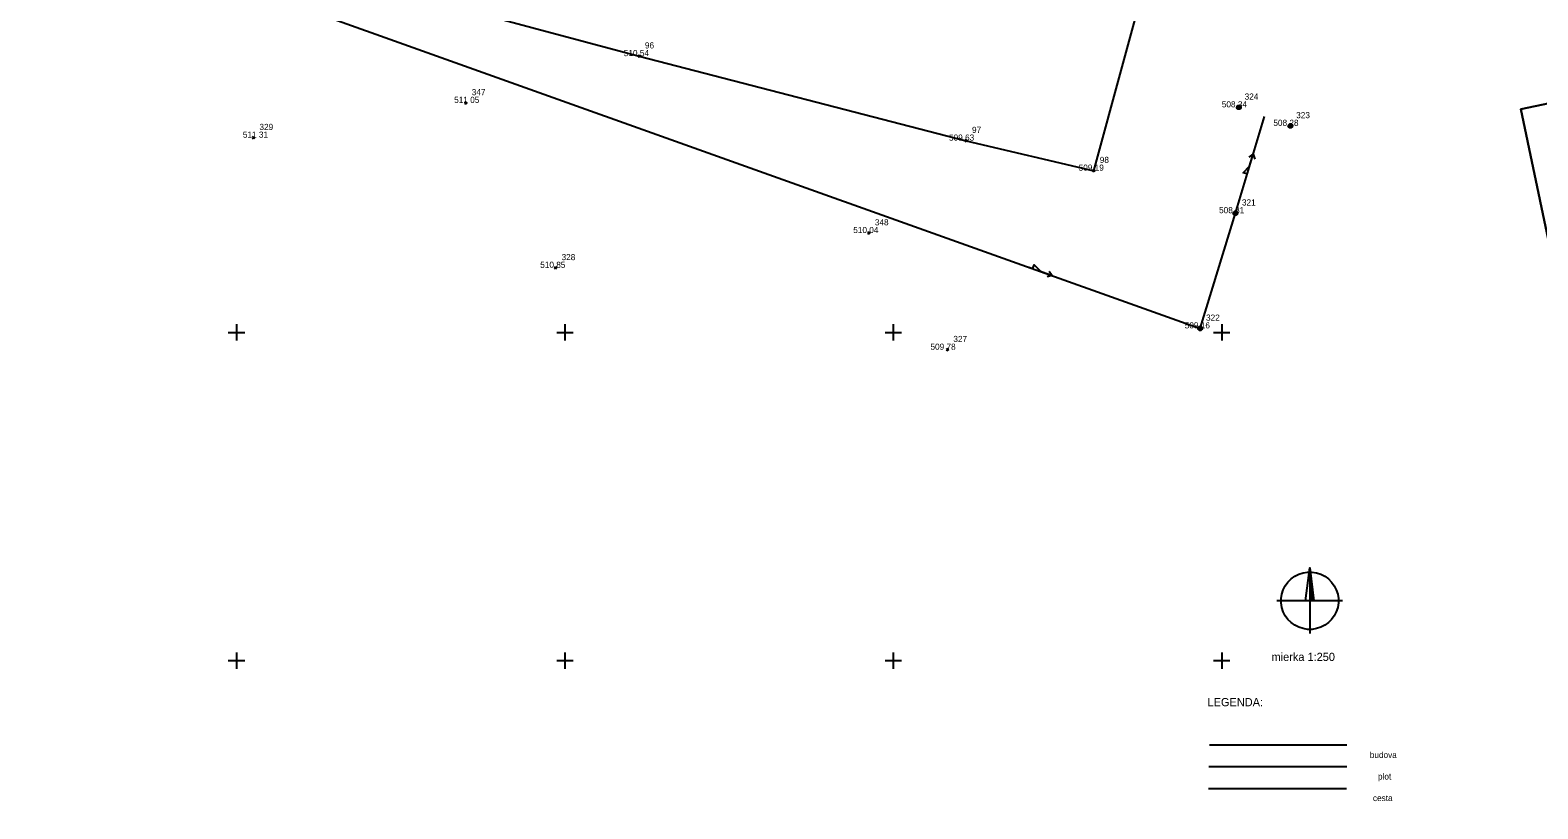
# Model space of a CAD drawing. Extents: x -408550 to -407654, y -1233019 to -1231230.
# Drawn here: x -407992.6 to -407900.7, y -1232149 to -1232101.6 of the extents above; entities that cross this region are included whole.
import ezdxf

# ---------------------------------------------------------------- set-up
doc = ezdxf.new("R2010")
doc.units = 0
for name, color, linetype in [('Level 1', 7, 'Continuous'), ('Level 11', 7, 'Continuous'), ('Level 12', 7, 'Continuous'), ('Level 14', 7, 'Continuous'), ('Level 22', 7, 'Continuous'), ('Level 23', 7, 'Continuous'), ('Level 25', 7, 'Continuous'), ('Level 26', 7, 'Continuous'), ('Level 40', 7, 'Continuous'), ('Level 45', 7, 'Continuous')]:
    doc.layers.add(name, color=color, linetype=linetype)

msp = doc.modelspace()

# ---------------------------------------------------------------- linework, layer by layer
at = {"layer": 'Level 1'}
for p, q in [((-407980.5, -1232120), (-407979.5, -1232120)), ((-407980, -1232119.5), (-407980, -1232120.5)), ((-407960.5, -1232120), (-407959.5, -1232120)), ((-407960, -1232119.5), (-407960, -1232120.5)), ((-407940.5, -1232120), (-407939.5, -1232120)), ((-407940, -1232119.5), (-407940, -1232120.5)), ((-407920.5, -1232120), (-407919.5, -1232120)), ((-407920, -1232119.5), (-407920, -1232120.5)), ((-407980, -1232139.5), (-407980, -1232140.5)), ((-407960, -1232139.5), (-407960, -1232140.5)), ((-407940, -1232139.5), (-407940, -1232140.5)), ((-407920, -1232139.5), (-407920, -1232140.5)), ((-407980.5, -1232140), (-407979.5, -1232140)), ((-407960.5, -1232140), (-407959.5, -1232140)), ((-407940.5, -1232140), (-407939.5, -1232140)), ((-407920.5, -1232140), (-407919.5, -1232140))]:
    msp.add_line(p, q, dxfattribs=at)
for points in [[(-408044.77, -1232071.09), (-408035.27, -1232074.4), (-408023.96, -1232078.34), (-408004.8, -1232085.03), (-407985.8, -1232091.65), (-407974.67, -1232095.53), (-407964.75, -1232098.99), (-407959.41, -1232100.85), (-407865.11, -1232098.76), (-407866.39, -1232098.97), (-407901.79, -1232106.39), (-407899.44, -1232117.51), (-407894.61, -1232140.35), (-407874.15, -1232135.48), (-407862.74, -1232131.55), (-407855.39, -1232125.61), (-407852.28, -1232122.69), (-407848.72, -1232121.07), (-407838.47, -1232120.5), (-407847.32, -1232123.67), (-407848.36, -1232134.5), (-407841.61, -1232145.17), (-407846.34, -1232175.35)], [(-407899.44, -1232117.51), (-407901.79, -1232106.39), (-407866.39, -1232098.97)], [(-407914.889, -1232136.352), (-407914.639, -1232134.352), (-407914.389, -1232136.352), (-407914.409, -1232136.332), (-407914.409, -1232136.212), (-407914.429, -1232136.052), (-407914.429, -1232136.332), (-407914.449, -1232136.332), (-407914.449, -1232135.892), (-407914.469, -1232135.732), (-407914.469, -1232136.332), (-407914.489, -1232136.332), (-407914.489, -1232135.572), (-407914.509, -1232135.432), (-407914.509, -1232136.332), (-407914.529, -1232136.332), (-407914.529, -1232135.272), (-407914.549, -1232135.092), (-407914.549, -1232136.332), (-407914.569, -1232136.332), (-407914.569, -1232134.952), (-407914.589, -1232134.772), (-407914.589, -1232136.332), (-407914.609, -1232136.332), (-407914.609, -1232134.612), (-407914.629, -1232134.452), (-407914.629, -1232136.332)], [(-407914.639, -1232134.352), (-407914.639, -1232138.352)], [(-407912.639, -1232136.352), (-407916.639, -1232136.352)]]:
    msp.add_lwpolyline(points, dxfattribs=at)
msp.add_lwpolyline([(-407914.501, -1232134.607), (-407914.231, -1232134.649), (-407913.971, -1232134.734), (-407913.726, -1232134.859), (-407913.504, -1232135.022), (-407913.309, -1232135.217), (-407913.146, -1232135.439), (-407913.021, -1232135.684), (-407912.936, -1232135.944), (-407912.894, -1232136.214), (-407912.894, -1232136.489), (-407912.936, -1232136.759), (-407913.021, -1232137.019), (-407913.146, -1232137.264), (-407913.309, -1232137.487), (-407913.504, -1232137.682), (-407913.726, -1232137.844), (-407913.971, -1232137.969), (-407914.231, -1232138.054), (-407914.501, -1232138.097), (-407914.776, -1232138.097), (-407915.046, -1232138.054), (-407915.306, -1232137.969), (-407915.551, -1232137.844), (-407915.774, -1232137.682), (-407915.969, -1232137.487), (-407916.131, -1232137.264), (-407916.256, -1232137.019), (-407916.341, -1232136.759), (-407916.384, -1232136.489), (-407916.384, -1232136.214), (-407916.341, -1232135.944), (-407916.256, -1232135.684), (-407916.131, -1232135.439), (-407915.969, -1232135.217), (-407915.774, -1232135.022), (-407915.551, -1232134.859), (-407915.306, -1232134.734), (-407915.046, -1232134.649), (-407914.776, -1232134.607)], close=True, dxfattribs=at)
at = {"layer": 'Level 11'}
msp.add_line((-407912.383, -1232145.158), (-407920.742, -1232145.158), dxfattribs=at)
at = {"layer": 'Level 12'}
msp.add_line((-407912.383, -1232146.474), (-407920.787, -1232146.474), dxfattribs=at)
msp.add_lwpolyline([(-408056.73, -1232038.31), (-408035.18, -1232049.43), (-408016.67, -1232058.98), (-407995.64, -1232070.23), (-407983.94, -1232082.87), (-407968.55, -1232099.65), (-407955.47, -1232103.17), (-407935.56, -1232108.32), (-407927.78, -1232110.15), (-407922.43, -1232090.45), (-407918.07, -1232073.76), (-407912.71, -1232053.79), (-407910.82, -1232047.19), (-407908.67, -1232042.13), (-407906.88, -1232038.31), (-407908.34, -1232037.12), (-407921.23, -1232026.55), (-407939.09, -1232011.64)], dxfattribs=at)
at = {"layer": 'Level 14'}
msp.add_line((-407912.406, -1232147.808), (-407920.806, -1232147.808), dxfattribs=at)
at = {"layer": 'Level 22'}
msp.add_line((-407927.78, -1232110.15), (-407927.78, -1232110.15), dxfattribs=at)
msp.add_lwpolyline([(-408151.19, -1232037.68), (-408071.39, -1232066.44), (-407993.81, -1232093.84), (-407921.31, -1232119.76), (-407919.17, -1232112.74), (-407917.389, -1232106.855)], dxfattribs=at)
at = {"layer": 'Level 23'}
for points in [[(-407955.401, -1232103.239), (-407955.539, -1232103.101)], [(-407955.539, -1232103.239), (-407955.401, -1232103.101)], [(-407965.961, -1232106.089), (-407966.099, -1232105.951)], [(-407966.099, -1232106.089), (-407965.961, -1232105.951)], [(-407918.891, -1232106.359), (-407919.029, -1232106.221)], [(-407919.029, -1232106.359), (-407918.891, -1232106.221)], [(-407915.751, -1232107.489), (-407915.889, -1232107.351)], [(-407915.889, -1232107.489), (-407915.751, -1232107.351)], [(-407978.891, -1232108.209), (-407979.029, -1232108.071)], [(-407979.029, -1232108.209), (-407978.891, -1232108.071)], [(-407935.491, -1232108.389), (-407935.629, -1232108.251)], [(-407935.629, -1232108.389), (-407935.491, -1232108.251)], [(-407927.711, -1232110.219), (-407927.849, -1232110.081)], [(-407927.849, -1232110.219), (-407927.711, -1232110.081)], [(-407919.101, -1232112.809), (-407919.239, -1232112.671)], [(-407919.239, -1232112.809), (-407919.101, -1232112.671)], [(-407941.411, -1232114.019), (-407941.549, -1232113.881)], [(-407941.549, -1232114.019), (-407941.411, -1232113.881)], [(-407960.491, -1232116.139), (-407960.629, -1232116.001)], [(-407960.629, -1232116.139), (-407960.491, -1232116.001)], [(-407921.241, -1232119.829), (-407921.379, -1232119.691)], [(-407921.379, -1232119.829), (-407921.241, -1232119.691)], [(-407936.631, -1232121.129), (-407936.769, -1232120.991)], [(-407936.769, -1232121.129), (-407936.631, -1232120.991)]]:
    msp.add_lwpolyline(points, dxfattribs=at)
at = {"layer": 'Level 25'}
for points in [[(-407918.518, -1232110.585), (-407918.446, -1232110.346), (-407918.685, -1232110.273), (-407918.301, -1232109.867), (-407918.084, -1232109.149)], [(-407918.336, -1232109.334), (-407918.084, -1232109.149), (-407917.977, -1232109.443)], [(-407931.744, -1232116.027), (-407931.509, -1232116.111), (-407931.425, -1232115.876), (-407931.038, -1232116.279), (-407930.332, -1232116.532)], [(-407930.504, -1232116.271), (-407930.332, -1232116.532), (-407930.63, -1232116.624)]]:
    msp.add_lwpolyline(points, dxfattribs=at)
at = {"layer": 'Level 45'}
for points in [[(-407918.999, -1232106.171), (-407918.921, -1232106.171), (-407918.859, -1232106.216), (-407918.835, -1232106.29), (-407918.859, -1232106.364), (-407918.921, -1232106.409), (-407918.999, -1232106.409), (-407919.061, -1232106.364), (-407919.085, -1232106.29), (-407919.061, -1232106.216), (-407918.999, -1232106.171), (-407918.99, -1232106.18), (-407918.93, -1232106.18), (-407918.89, -1232106.2), (-407919.03, -1232106.2), (-407919.05, -1232106.22), (-407918.87, -1232106.22), (-407918.87, -1232106.24), (-407919.05, -1232106.24), (-407919.06, -1232106.26), (-407918.86, -1232106.26), (-407918.85, -1232106.28), (-407919.07, -1232106.28), (-407919.07, -1232106.3), (-407918.85, -1232106.3), (-407918.858, -1232106.32), (-407919.061, -1232106.32), (-407919.06, -1232106.34), (-407918.858, -1232106.34), (-407918.87, -1232106.36), (-407919.05, -1232106.36), (-407919.03, -1232106.38), (-407918.89, -1232106.38), (-407918.917, -1232106.4), (-407919.002, -1232106.4)], [(-407915.859, -1232107.301), (-407915.781, -1232107.301), (-407915.719, -1232107.346), (-407915.695, -1232107.42), (-407915.719, -1232107.493), (-407915.781, -1232107.539), (-407915.859, -1232107.539), (-407915.921, -1232107.493), (-407915.945, -1232107.42), (-407915.921, -1232107.346), (-407915.859, -1232107.301), (-407915.85, -1232107.31), (-407915.79, -1232107.31), (-407915.75, -1232107.33), (-407915.89, -1232107.33), (-407915.91, -1232107.35), (-407915.73, -1232107.35), (-407915.73, -1232107.37), (-407915.91, -1232107.37), (-407915.92, -1232107.39), (-407915.72, -1232107.39), (-407915.71, -1232107.41), (-407915.93, -1232107.41), (-407915.93, -1232107.43), (-407915.71, -1232107.43), (-407915.718, -1232107.45), (-407915.921, -1232107.45), (-407915.92, -1232107.47), (-407915.718, -1232107.47), (-407915.73, -1232107.49), (-407915.91, -1232107.49), (-407915.89, -1232107.51), (-407915.75, -1232107.51), (-407915.777, -1232107.53), (-407915.862, -1232107.53)], [(-407919.209, -1232112.621), (-407919.131, -1232112.621), (-407919.069, -1232112.666), (-407919.045, -1232112.74), (-407919.069, -1232112.814), (-407919.131, -1232112.859), (-407919.209, -1232112.859), (-407919.271, -1232112.814), (-407919.295, -1232112.74), (-407919.271, -1232112.666), (-407919.209, -1232112.621), (-407919.2, -1232112.63), (-407919.14, -1232112.63), (-407919.1, -1232112.65), (-407919.24, -1232112.65), (-407919.26, -1232112.67), (-407919.08, -1232112.67), (-407919.08, -1232112.69), (-407919.26, -1232112.69), (-407919.27, -1232112.71), (-407919.07, -1232112.71), (-407919.06, -1232112.73), (-407919.28, -1232112.73), (-407919.28, -1232112.75), (-407919.06, -1232112.75), (-407919.068, -1232112.77), (-407919.271, -1232112.77), (-407919.27, -1232112.79), (-407919.068, -1232112.79), (-407919.08, -1232112.81), (-407919.26, -1232112.81), (-407919.24, -1232112.83), (-407919.1, -1232112.83), (-407919.127, -1232112.85), (-407919.212, -1232112.85)], [(-407921.349, -1232119.641), (-407921.271, -1232119.641), (-407921.209, -1232119.686), (-407921.185, -1232119.76), (-407921.209, -1232119.834), (-407921.271, -1232119.879), (-407921.349, -1232119.879), (-407921.411, -1232119.834), (-407921.435, -1232119.76), (-407921.411, -1232119.686), (-407921.349, -1232119.641), (-407921.34, -1232119.65), (-407921.28, -1232119.65), (-407921.24, -1232119.67), (-407921.38, -1232119.67), (-407921.4, -1232119.69), (-407921.22, -1232119.69), (-407921.22, -1232119.71), (-407921.4, -1232119.71), (-407921.41, -1232119.73), (-407921.21, -1232119.73), (-407921.2, -1232119.75), (-407921.42, -1232119.75), (-407921.42, -1232119.77), (-407921.2, -1232119.77), (-407921.208, -1232119.79), (-407921.411, -1232119.79), (-407921.41, -1232119.81), (-407921.208, -1232119.81), (-407921.22, -1232119.83), (-407921.4, -1232119.83), (-407921.38, -1232119.85), (-407921.24, -1232119.85), (-407921.267, -1232119.87), (-407921.352, -1232119.87)]]:
    msp.add_lwpolyline(points, dxfattribs=at)

# ---------------------------------------------------------------- texts
at = {"layer": 'Level 1'}
for s, height, p in [('mierka 1:250', 0.5, (-407916.968, -1232140.023)), ('LEGENDA:', 0.5, (-407920.864, -1232142.782)), ('budova', 0.375, (-407910.982, -1232145.935)), ('plot', 0.375, (-407910.484, -1232147.248)), ('cesta', 0.375, (-407910.79, -1232148.56))]:
    msp.add_text(s, height=height, dxfattribs=at).set_placement(p)
at = {"layer": 'Level 26'}
for s, p in [('96', (-407955.128, -1232102.7)), ('347', (-407965.674, -1232105.55)), ('324', (-407918.604, -1232105.82)), ('329', (-407978.605, -1232107.67)), ('97', (-407935.207, -1232107.85)), ('323', (-407915.464, -1232106.95)), ('98', (-407927.427, -1232109.68)), ('321', (-407918.769, -1232112.27)), ('348', (-407941.124, -1232113.48)), ('328', (-407960.204, -1232115.6)), ('322', (-407920.954, -1232119.29)), ('327', (-407936.344, -1232120.59))]:
    msp.add_text(s, height=0.375, dxfattribs=at).set_placement(p)
at = {"layer": 'Level 40'}
for s, p in [('510 54', (-407956.414, -1232103.17)), ('511 05', (-407966.745, -1232106.02)), ('508 34', (-407919.994, -1232106.29)), ('508 28', (-407916.854, -1232107.42)), ('511 31', (-407979.615, -1232108.14)), ('509 63', (-407936.607, -1232108.32)), ('509 19', (-407928.712, -1232110.15)), ('508 81', (-407920.16, -1232112.74)), ('510 04', (-407942.44, -1232113.95)), ('510 85', (-407961.504, -1232116.07)), ('509 16', (-407922.251, -1232119.76)), ('509 78', (-407937.737, -1232121.06))]:
    msp.add_text(s, height=0.375, dxfattribs=at).set_placement(p)

doc.saveas('drawing.dxf')
